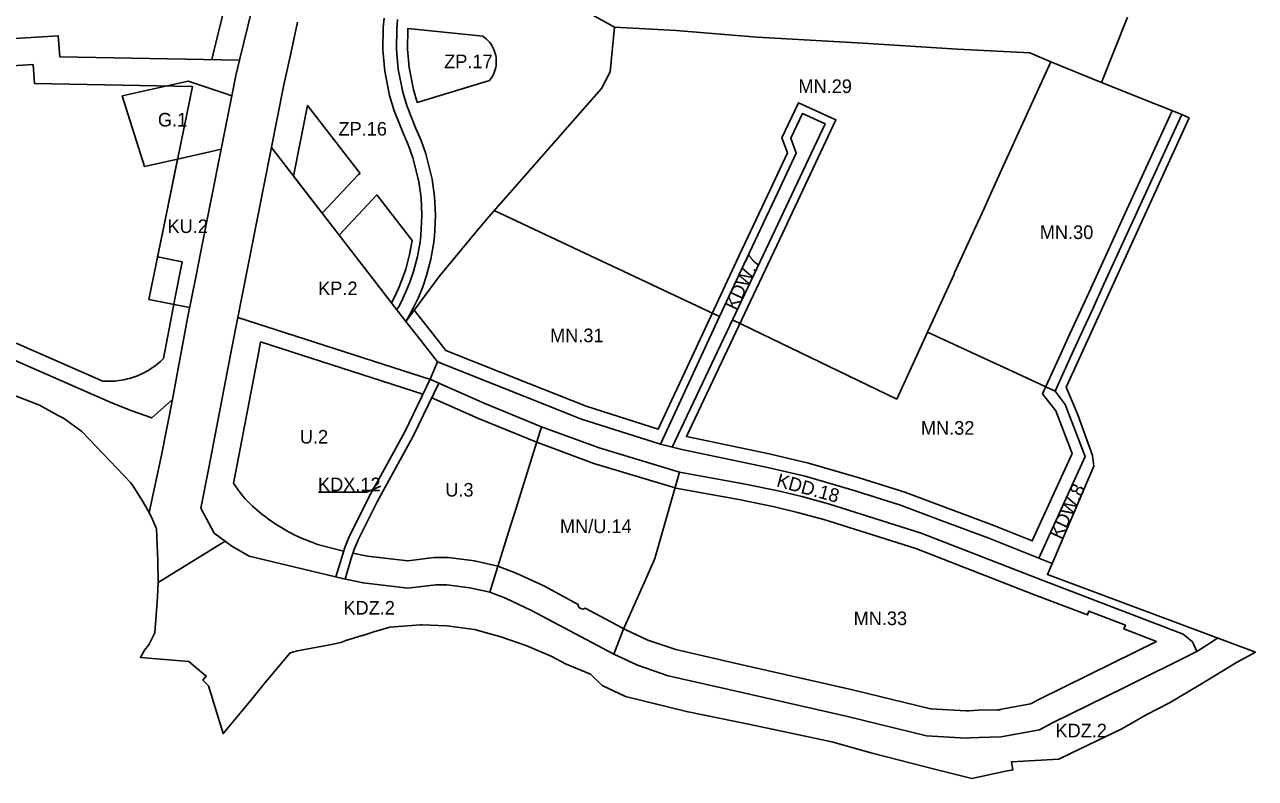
# Model space of a CAD drawing. Extents: x 7416945 to 7418410, y 5548550 to 5549803.
# Drawn here: x 7417372.5 to 7417825.4, y 5548550.4 to 5548827.7 of the extents above; entities that cross this region are included whole.
import ezdxf

# ---------------------------------------------------------------- set-up
doc = ezdxf.new("R2010")
doc.units = 0
for name, color, linetype in [('linie rozgraniczające', 7, 'Continuous'), ('nieprzekraczalna linia lokalizacyjna', 7, 'Continuous'), ('nieprzekraczalne linie zabudowy', 7, 'Continuous'), ('przeznaczenia terenów', 7, 'Continuous')]:
    doc.layers.add(name, color=color, linetype=linetype)

msp = doc.modelspace()

# ---------------------------------------------------------------- linework, layer by layer
at = {"layer": 'linie rozgraniczające'}
for p, q in [((7417545.3, 5548759.27), (7417628.2, 5548720.27)), ((7417433.21, 5548723.56), (7417418.24, 5548726.61)), ((7417632.92, 5548719.03), (7417693.46, 5548689.85)), ((7417704.73, 5548714.54), (7417693.46, 5548689.85)), ((7417521.71, 5548697.2), (7417524.43, 5548703.66)), ((7417446.25, 5548637.67), (7417421.67, 5548622.47))]:
    msp.add_line(p, q, dxfattribs=at)
for points in [[(7417461.13, 5548853.66), (7417451.56, 5548814.61), (7417450.19, 5548809.01), (7417448.69, 5548801.49), (7417444.79, 5548781.83), (7417437.17, 5548743.56), (7417435.55, 5548735.37), (7417432.44, 5548719.68), (7417428.92, 5548701.13), (7417426.84, 5548689.83), (7417422.83, 5548669.24), (7417418.25, 5548648.17)], [(7417570.23, 5548837.5), (7417589.55, 5548826.76), (7417587.91, 5548810.29), (7417584.76, 5548804.15), (7417543.15, 5548756.83), (7417539.16, 5548752.01), (7417525.02, 5548734.98), (7417512.78, 5548718.47)], [(7417778.25, 5548830.48), (7417768.76, 5548806.39), (7417772.81, 5548804.77), (7417780.43, 5548801.72), (7417798.24, 5548794.6), (7417800.94, 5548793.37), (7417782.23, 5548752.35), (7417759.26, 5548702), (7417755.76, 5548694.32), (7417759.97, 5548684.16), (7417765.44, 5548669.23), (7417765.95, 5548665.31), (7417748.84, 5548625.45), (7417825.36, 5548596.8), (7417818.42, 5548593.08), (7417804.9, 5548584.79), (7417793.81, 5548578.25), (7417785.15, 5548573.74), (7417776.22, 5548568.68), (7417757.54, 5548559.68), (7417753, 5548557.49), (7417735.62, 5548556.51), (7417736.16, 5548553.53), (7417732.9, 5548552.89), (7417721.07, 5548550.4), (7417707.8, 5548553.61), (7417684.38, 5548559.68), (7417681.33, 5548560.52), (7417669.52, 5548563.87), (7417657.32, 5548566.44), (7417639.5, 5548570.19), (7417616.6, 5548574.85), (7417615.97, 5548575.02), (7417593.64, 5548580.53), (7417585.04, 5548584.56), (7417580.69, 5548588.72), (7417571.46, 5548592.52), (7417566.48, 5548595.18), (7417557.22, 5548599.2), (7417547.38, 5548602.63), (7417545.45, 5548603.14), (7417537.99, 5548605.11), (7417527.81, 5548606.57), (7417518.77, 5548606.86), (7417518.1, 5548606.89), (7417506.87, 5548606.04), (7417500.96, 5548604.25), (7417496.88, 5548602.99), (7417496.74, 5548602.95), (7417490.71, 5548601.08), (7417488.84, 5548600.34), (7417485.43, 5548599.69), (7417472.94, 5548597.38), (7417470.19, 5548596.6), (7417460.53, 5548585.02), (7417456.11, 5548579.52), (7417445.56, 5548566.89), (7417440.15, 5548584.4), (7417438.06, 5548586.52), (7417439.3, 5548588.02), (7417432.93, 5548593.42), (7417415.07, 5548594.87), (7417416.61, 5548597.52), (7417418.14, 5548599.5), (7417420.43, 5548603.96), (7417421.37, 5548617.07), (7417421.67, 5548622.47), (7417421.55, 5548630.42), (7417421.02, 5548642.14), (7417419.57, 5548645.59), (7417418.25, 5548648.17), (7417417.33, 5548649.96), (7417415.34, 5548653.2), (7417412.46, 5548657.88), (7417411.59, 5548659.14), (7417393.48, 5548678.04), (7417386.79, 5548682.86), (7417384.56, 5548684.07), (7417377.99, 5548687.66), (7417357.62, 5548695.58)], [(7417472.9, 5548828.6), (7417470.41, 5548817.08), (7417467.92, 5548805.57), (7417458.3, 5548757.17), (7417448.69, 5548708.78), (7417440.22, 5548664.62), (7417437.35, 5548649.81)], [(7417504.73, 5548830.04), (7417504.44, 5548826.63), (7417504.34, 5548818.29), (7417505.03, 5548810.6), (7417506.8, 5548801.6), (7417508.48, 5548795.96), (7417511.87, 5548787.55), (7417513.77, 5548783.17), (7417515.38, 5548778.65), (7417517.55, 5548769.91), (7417518.37, 5548763.96), (7417518.68, 5548757.42), (7417518.3, 5548750.16), (7417518, 5548747.66), (7417517.05, 5548742.42), (7417515.59, 5548736.83), (7417514.27, 5548732.96), (7417512.81, 5548729.35), (7417511.04, 5548725.62), (7417510.03, 5548723.72), (7417509.33, 5548722.93)], [(7417509.71, 5548829.52), (7417509.44, 5548826.38), (7417509.34, 5548818.49), (7417509.98, 5548811.3), (7417511.66, 5548802.8), (7417513.2, 5548797.61), (7417516.48, 5548789.48), (7417518.42, 5548785.01), (7417520.17, 5548780.09), (7417522.47, 5548770.86), (7417523.35, 5548764.42), (7417523.68, 5548757.41), (7417523.29, 5548749.73), (7417522.94, 5548746.91), (7417521.94, 5548741.34), (7417520.38, 5548735.39), (7417518.96, 5548731.21), (7417517.39, 5548727.34), (7417515.51, 5548723.37), (7417514.16, 5548720.83), (7417512.78, 5548718.47)], [(7417768.76, 5548806.39), (7417750.14, 5548814.03), (7417742.36, 5548817.34), (7417715.71, 5548818.68), (7417681.06, 5548820.86), (7417642.02, 5548823.03), (7417612.17, 5548825.55), (7417589.55, 5548826.76)], [(7417451.56, 5548814.61), (7417385.39, 5548815.89), (7417384.85, 5548823.57), (7417287.02, 5548817.49)], [(7417751.63, 5548692.81), (7417734.29, 5548700.91), (7417726.97, 5548704.28), (7417704.73, 5548714.54), (7417714.47, 5548735.88), (7417714.7, 5548736.38), (7417719.58, 5548747.07), (7417720.9, 5548749.97), (7417722.45, 5548753.36), (7417725.52, 5548760.08), (7417728.49, 5548766.61), (7417733.96, 5548778.58), (7417750.14, 5548814.03)], [(7417428.78, 5548778.22), (7417416.6, 5548775.47), (7417408.4, 5548801.46), (7417432.66, 5548806.88), (7417445.9, 5548802.47), (7417448.69, 5548801.49)], [(7417610.8, 5548672.27), (7417648.6, 5548752.17), (7417667.02, 5548791.15), (7417658.69, 5548794.98), (7417654.41, 5548785.94), (7417656.43, 5548780.39), (7417649.47, 5548765.66), (7417637.09, 5548739.42), (7417628.2, 5548720.27), (7417606.41, 5548673.32)], [(7417745.67, 5548631.41), (7417762.67, 5548668.84), (7417755.4, 5548687.94), (7417751.63, 5548692.81), (7417757.22, 5548705.08), (7417760.66, 5548712.62), (7417765.49, 5548723.16), (7417769.65, 5548732.24), (7417780.29, 5548755.42), (7417784.46, 5548764.51), (7417798.24, 5548794.6)], [(7417444.79, 5548781.83), (7417440.65, 5548780.9), (7417428.78, 5548778.22), (7417423.46, 5548752.17), (7417418.24, 5548726.61)], [(7417524.43, 5548703.66), (7417517.85, 5548711.91), (7417512.78, 5548718.47), (7417463.32, 5548782.42)], [(7417523.85, 5548696.32), (7417522.25, 5548697.03), (7417450.91, 5548719.94)], [(7417367.02, 5548704.93), (7417396.96, 5548691.82), (7417404.78, 5548688.46), (7417411.98, 5548685.63), (7417419.23, 5548683.03), (7417426.84, 5548689.83)], [(7417750.56, 5548629.45), (7417745.67, 5548631.41), (7417727.25, 5548638.79), (7417708.81, 5548645.69), (7417694.76, 5548650.95), (7417678.08, 5548656.18), (7417659.71, 5548661.54), (7417645.34, 5548664.88), (7417614.31, 5548671.43), (7417606.41, 5548673.32), (7417577.39, 5548682.57), (7417556.19, 5548691.03), (7417524.43, 5548703.66)], [(7417521.71, 5548697.2), (7417512.35, 5548677.86), (7417503.42, 5548661.61), (7417499.12, 5548653.8), (7417496.05, 5548647.54), (7417492.04, 5548639.67), (7417490.26, 5548635.34), (7417489.03, 5548631.27), (7417486.97, 5548624.49)], [(7417524.93, 5548695.84), (7417515.46, 5548676.25), (7417506.49, 5548659.93), (7417502.23, 5548652.19), (7417499.18, 5548645.97), (7417495.17, 5548638.1), (7417493.69, 5548634.58), (7417492.57, 5548630.87), (7417490.39, 5548623.7)], [(7417803.82, 5548597.02), (7417802.2, 5548600.67), (7417798.76, 5548603.48), (7417746.26, 5548623.54), (7417702.4, 5548640.61), (7417668.29, 5548651.34), (7417658.43, 5548654.05), (7417649.7, 5548656.14), (7417636.37, 5548658.86), (7417613.5, 5548663.02), (7417583.86, 5548671.94), (7417562.73, 5548679.75), (7417541.86, 5548688.3), (7417523.85, 5548696.32)], [(7417562.73, 5548679.75), (7417552.74, 5548647.88), (7417551.18, 5548642.94), (7417543.61, 5548618.9)], [(7417613.5, 5548663.02), (7417604.34, 5548631.32), (7417600.99, 5548623.41), (7417592.76, 5548605.1), (7417589.23, 5548596.04)], [(7417437.35, 5548649.81), (7417442.19, 5548640.63), (7417448.74, 5548635.85), (7417455.15, 5548632.16), (7417489.4, 5548623.91), (7417497, 5548622.31), (7417513.51, 5548620.37)], [(7417731.81, 5548565.67), (7417727.79, 5548565.57), (7417723.76, 5548565.46), (7417720.5, 5548565.29), (7417718.88, 5548565.2), (7417704.36, 5548566.05), (7417674.8, 5548573.26), (7417631.63, 5548583.05), (7417609.32, 5548588.12), (7417598.02, 5548592), (7417589.23, 5548596.04), (7417559.02, 5548612.21), (7417549.41, 5548616.67), (7417543.61, 5548618.9), (7417536.31, 5548620.54), (7417527.84, 5548621.61), (7417523.81, 5548621.61), (7417513.51, 5548620.37)], [(7417811.43, 5548602.02), (7417808.97, 5548600.36), (7417807.86, 5548599.61), (7417803.82, 5548597.02), (7417777.17, 5548583.83), (7417750.48, 5548570.71), (7417745.97, 5548568.24), (7417731.81, 5548565.67)]]:
    msp.add_lwpolyline(points, dxfattribs=at)
at = {"layer": 'nieprzekraczalna linia lokalizacyjna'}
for points in [[(7417516.94, 5548799.08), (7417543.56, 5548807.16), (7417544.35, 5548808.33), (7417544.75, 5548809.01), (7417545.09, 5548809.71), (7417545.38, 5548810.44), (7417545.62, 5548811.18), (7417545.81, 5548811.93), (7417545.94, 5548812.68), (7417546.02, 5548813.44), (7417546.04, 5548814.18), (7417546.02, 5548814.91), (7417545.95, 5548815.64), (7417545.82, 5548816.38), (7417545.65, 5548817.11), (7417545.42, 5548817.84), (7417545.14, 5548818.56), (7417544.8, 5548819.26), (7417544.42, 5548819.95), (7417543.98, 5548820.6), (7417543.51, 5548821.22), (7417542.98, 5548821.8), (7417542.43, 5548822.35), (7417541.84, 5548822.85), (7417541.07, 5548823.41), (7417513.43, 5548826.21), (7417513.34, 5548818.64), (7417513.95, 5548811.87), (7417515.55, 5548803.76), (7417516.94, 5548799.08)], [(7417495.92, 5548772.96), (7417476.6, 5548797.94), (7417471.43, 5548771.93)], [(7417471.43, 5548771.93), (7417481.97, 5548758.3)], [(7417481.97, 5548758.3), (7417495.17, 5548772.37), (7417495.92, 5548772.96)], [(7417507.48, 5548725.32), (7417508.36, 5548726.97), (7417510.06, 5548730.55), (7417511.46, 5548734), (7417512.71, 5548737.7), (7417514.12, 5548743.07), (7417515.05, 5548748.22), (7417502.04, 5548765.04), (7417488.18, 5548750.27), (7417507.48, 5548725.32)]]:
    msp.add_lwpolyline(points, dxfattribs=at)
at = {"layer": 'nieprzekraczalne linie zabudowy'}
for points in [[(7417441.31, 5548814.81), (7417441.85, 5548816.99), (7417451.42, 5548856.04), (7417457.85, 5548882.34), (7417461.75, 5548900.04), (7417372.05, 5548895.61), (7417298.16, 5548891.96), (7417293.26, 5548889.42), (7417290.97, 5548884.14), (7417292.69, 5548828.47), (7417292.73, 5548826.87), (7417301.25, 5548827.4), (7417301.53, 5548818.39)], [(7417369.4, 5548710.44), (7417399.35, 5548697.32), (7417401.17, 5548696.54), (7417402.67, 5548696.47), (7417404.18, 5548696.48), (7417404.94, 5548696.51), (7417405.71, 5548696.57), (7417406.47, 5548696.64), (7417407.24, 5548696.74), (7417408, 5548696.86), (7417408.76, 5548697), (7417409.52, 5548697.15), (7417410.28, 5548697.33), (7417411.03, 5548697.53), (7417411.78, 5548697.75), (7417412.52, 5548697.99), (7417413.26, 5548698.25), (7417413.99, 5548698.53), (7417414.71, 5548698.83), (7417415.42, 5548699.15), (7417416.12, 5548699.49), (7417416.81, 5548699.85), (7417417.49, 5548700.22), (7417418.16, 5548700.61), (7417418.81, 5548701.02), (7417419.46, 5548701.45), (7417420.09, 5548701.89), (7417420.7, 5548702.34), (7417421.3, 5548702.81), (7417422.46, 5548703.79), (7417423.55, 5548704.81), (7417427.09, 5548723.46), (7417427.88, 5548727.43), (7417430.21, 5548739.19), (7417430.45, 5548740.43), (7417421.43, 5548742.21), (7417423.46, 5548752.17), (7417434.23, 5548804.94), (7417376.06, 5548806.07), (7417375.57, 5548812.97), (7417293.31, 5548807.86)], [(7417515.87, 5548722.64), (7417521.78, 5548715), (7417527.51, 5548707.82), (7417558.04, 5548695.67), (7417579.08, 5548687.28), (7417605.65, 5548678.81), (7417610.69, 5548689.66), (7417615.39, 5548699.8), (7417634.37, 5548740.69), (7417646.76, 5548766.94), (7417653.18, 5548780.54), (7417651.16, 5548786.09), (7417657.25, 5548798.94), (7417671.03, 5548792.61), (7417651.31, 5548750.89), (7417615.97, 5548676.19), (7417646.43, 5548669.76), (7417660.98, 5548666.38), (7417679.53, 5548660.97), (7417696.39, 5548655.68), (7417729.06, 5548643.45), (7417743.28, 5548637.76), (7417757.91, 5548669.96), (7417751.96, 5548685.58), (7417747.08, 5548691.89), (7417753.67, 5548706.36), (7417757.11, 5548713.9), (7417761.94, 5548724.44), (7417766.1, 5548733.52), (7417776.74, 5548756.71), (7417780.91, 5548765.79), (7417794.74, 5548796)], [(7417519.07, 5548691.75), (7417459.31, 5548710.94), (7417458.5, 5548706.86), (7417450.04, 5548662.72), (7417449.32, 5548659.04), (7417450.64, 5548657.08), (7417451.2, 5548656.29), (7417451.78, 5548655.52), (7417452.38, 5548654.76), (7417452.99, 5548654.02), (7417453.63, 5548653.29), (7417454.28, 5548652.58), (7417454.94, 5548651.89), (7417455.63, 5548651.22), (7417456.33, 5548650.57), (7417457.2, 5548649.78), (7417458.08, 5548649.02), (7417458.98, 5548648.26), (7417459.9, 5548647.52), (7417460.83, 5548646.8), (7417461.77, 5548646.09), (7417462.73, 5548645.39), (7417463.71, 5548644.72), (7417464.69, 5548644.05), (7417465.69, 5548643.41), (7417466.7, 5548642.78), (7417467.72, 5548642.17), (7417468.76, 5548641.58), (7417469.8, 5548641.01), (7417470.86, 5548640.46), (7417471.92, 5548639.92), (7417473, 5548639.41), (7417474.08, 5548638.91), (7417475.17, 5548638.43), (7417476.27, 5548637.97), (7417477.38, 5548637.54), (7417478.49, 5548637.12), (7417479.61, 5548636.72), (7417480.74, 5548636.35), (7417489.87, 5548634.03)], [(7417493.3, 5548633.3), (7417498.62, 5548632.19), (7417513.49, 5548630.44), (7417523.2, 5548631.61), (7417528.47, 5548631.61), (7417538.04, 5548630.4), (7417546.62, 5548628.47), (7417546.62, 5548628.45), (7417553.31, 5548625.89), (7417563.49, 5548621.17), (7417576.15, 5548614.38), (7417576.18, 5548613.95), (7417576.42, 5548613.43), (7417576.88, 5548612.97), (7417577.39, 5548612.74), (7417577.98, 5548612.7), (7417578.51, 5548612.84), (7417578.75, 5548612.99), (7417593.68, 5548605), (7417601.74, 5548601.29), (7417612.05, 5548597.75), (7417633.84, 5548592.81), (7417677.1, 5548583), (7417705.85, 5548575.98), (7417718.89, 5548575.22), (7417719.96, 5548575.28), (7417723.37, 5548575.45), (7417731.55, 5548575.67), (7417730.02, 5548575.51), (7417742.59, 5548577.79), (7417745.87, 5548579.59), (7417772.75, 5548592.8), (7417788.94, 5548600.81), (7417777, 5548605.37), (7417777.54, 5548606.82), (7417764.05, 5548611.9), (7417763.53, 5548610.52), (7417744.1, 5548617.95), (7417700.41, 5548634.95), (7417666.6, 5548645.59), (7417656.93, 5548648.24), (7417648.4, 5548650.28), (7417635.23, 5548652.97), (7417612.09, 5548657.18), (7417611.83, 5548657.26), (7417581.95, 5548666.25), (7417560.55, 5548674.16), (7417539.5, 5548682.78), (7417522.32, 5548690.43)]]:
    msp.add_lwpolyline(points, dxfattribs=at)
at = {"layer": 'przeznaczenia terenów'}
msp.add_lwpolyline([(7417480.65, 5548655.63), (7417498.34, 5548655.63), (7417503.55, 5548657.85)], dxfattribs=at)

# ---------------------------------------------------------------- texts
for s, p in [('ZP.17', (7417526.86, 5548811.65)), ('MN.29', (7417657.2, 5548802.52)), ('G.1', (7417421.53, 5548790.2)), ('ZP.16', (7417487.96, 5548786.85)), ('KU.2', (7417425.06, 5548751.01)), ('MN.30', (7417746.02, 5548748.81)), ('KP.2', (7417480.5, 5548728.16)), ('MN.31', (7417565.82, 5548710.85)), ('MN.32', (7417702.27, 5548676.83)), ('U.2', (7417473.74, 5548673.57)), ('KDX.12', (7417480.43, 5548656.03)), ('U.3', (7417527.27, 5548654.06)), ('MN/U.14', (7417569.47, 5548640.65)), ('KDZ.2', (7417489.78, 5548610.65)), ('MN.33', (7417677.51, 5548606.78)), ('KDZ.2', (7417751.79, 5548565.49))]:
    msp.add_text(s, height=5, dxfattribs=at).set_placement(p)
for s, rotation, p in [('KDW.7', 64.6984, (7417634.39, 5548722.25)), ('KDD.18', 344.7967, (7417648.84, 5548657.87)), ('KDW.8', 64.6984, (7417753.85, 5548638.05))]:
    msp.add_text(s, height=5, rotation=rotation, dxfattribs=at).set_placement(p)

doc.saveas('drawing.dxf')
